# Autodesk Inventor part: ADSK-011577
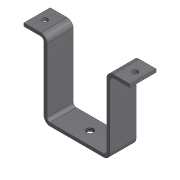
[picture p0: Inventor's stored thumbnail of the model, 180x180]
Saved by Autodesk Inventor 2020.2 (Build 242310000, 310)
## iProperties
Created: 2000-02
Part Number: ADSK-011577
Document SubType Name: Tôlerie
Description: FSHTPH,FH,XX,12,030,010,010,090,55X,BUMPER MOUNT
Designer: sspink
Material: 1.0312 DC05
Density: 1 g/cm^3
Sheet Metal Rule: Stahlblech 1.0312 - DC05 -   3.0 mm
Appearance: Metal-Steel(Polish)
Mass: 17.2489 g
Surface Area: 132.152 cm^2
Volume: 17.2489 cm^3
Flat Pattern Width: 2.5 cm
Flat Pattern Length: 23.2143 cm
Flat Pattern Area: 58.0358 cm^2
Sheet Metal Width: 25,000 mm
Sheet Metal Length: 232,143 mm
Sheet Metal Area: 5803,584 mm^2
Control State: 0
Checked Out: False
Master: False
Shininess: 60.0
Length Units: 11269
Angle Units: 11279
Time Units: 11290
Mass Units: 11283
Length Display Precision: 3
Angle Display Precision: 2
Compacted: True
Cutlength: 9.14
Material Desc: FLAT,HRS,0.125X1.00
Material_Number: A084348
G_L: 25x232,1 mm
Thickness: 3,000 mm
Dimensions: 73x25x101 mm
Mass: 0,017 kg
Semi finished: Stahlblech 1.0312 - DC05 -   3.0 mm
VLT_Material: 1.0312 DC05
Density: 7.86
Volumn: 5.8993430400000015
Area: 44.90313600000001
PropertySet Name: Model Information
Author: sspink
Revision Number: -
Title: FSHTPH,FH,XX,12,030,010,010,090,55X,BUMPER MOUNT
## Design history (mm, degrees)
node "Konturlasche1"
  sketch "Skizze10"
    geometry: L1 (-31.5, 0)-(31.5, 0); L2 (-31.5, 0)-(-31.5, 70); L3 (-31.5, 70)-(-50.5, 70); L4 (31.5, 0)-(31.5, 70); L5 (31.5, 70)-(50.5, 70); 2 further points
    constraints: 10 end point, 2 perpendicular, 2 vertical, 1 coincident, 1 horizontal, 1 midpoint
    dimensions: "d67" = 63 distance of L1.start L1.end; "d68" = 70 distance of L1.start L2.end; "d69" = 19 distance of L2.end L3.end; "d70" = 19 distance of L4.end L5.end (= d69)
sketch "Skizze11"
  geometry: 1 further point
hole "Bohrung5" sketch "Skizze11" at (25.5, -12.5) diameter "d81" = 6.647; stored, may be unused: countersink angle "d85" = 90 deg, drill point angle "d87" = 118 deg; dims "d82" = 16, "d83" = 4, "d84" = 2, "d86" = 3 (= Thickness)
sketch "Skizze12"
  geometry: L1 (-93.5, 12.5)-(-7.5, 12.5); 4 further points
  constraints: 3 coincident, 2 end point, 1 horizontal, 1 midpoint
  dimensions: "d89" = 86 distance of L1.start L1.end
hole "Bohrung6" sketch "Skizze12" at (-93.5, 12.5), (-7.5, 12.5) diameter "d90" = 5.5; stored, may be unused: countersink angle "d94" = 90 deg, drill point angle "d96" = 118 deg; dims "d91" = 16, "d92" = 12.6, "d93" = 2, "d95" = 3 (= Thickness)
node "Solide1"
node "Corps solides"
node "Corps surfaciques"
feature "Grobblech6" dims "d66" = 3 (= Thickness), "d71" = 3 (= BendReliefWidth), "d72" = 1.5 (= BendReliefDepth), "d73" = 6 (= MinimumRemnant), "d74" = 3 (= TransitionRadius), "d75" = 25, "d76" = 3 (= BendRadius), "d77" = 3, "d78" = 12 (= CornerReliefSize), "d79" = 3 (= TailleJeu), "d80" = 3 (= TailleRayonJacobi), "SeamGap" = 0.00508
feature "Biegung5" dims "d66" = 3 (= Thickness), "d71" = 3 (= BendReliefWidth), "d72" = 1.5 (= BendReliefDepth), "d73" = 6 (= MinimumRemnant), "d74" = 3 (= TransitionRadius), "d76" = 3 (= BendRadius), "d77" = 3, "SeamGap" = 0.00508
feature "Ecke1" dims "d77" = 3, "d78" = 12 (= CornerReliefSize), "d79" = 3 (= TailleJeu), "d80" = 3 (= TailleRayonJacobi)
feature "Definition1"
other parameters: "Thickness" = 3 (derived), "BendRadius" = 3 (= Thickness), "BendReliefWidth" = 3 (= Thickness), "BendReliefDepth" = 1.5 (= 0.5 x Thickness), "CornerReliefSize" = 12 (= 4 x Thickness), "MinimumRemnant" = 6 (= 2 x Thickness), "d2" = 3 (= BendRadius), "thickness" = 3.175 [user parameter], "TransitionRadius" = 3 (= BendRadius), "TailleRayonJacobi" = 3 (= BendRadius), "TailleJeu" = 3 (= Thickness), "thickness" = 3.175, "BendRadius" = 3, "BendReliefDepth" = 1.5, "BendReliefWidth" = 3, "CornerReliefSize" = 12, "MinimumRemnant" = 6, "TailleJeu" = 3, "TailleRayonJacobi" = 3, "Thickness" = 3, "TransitionRadius" = 3
